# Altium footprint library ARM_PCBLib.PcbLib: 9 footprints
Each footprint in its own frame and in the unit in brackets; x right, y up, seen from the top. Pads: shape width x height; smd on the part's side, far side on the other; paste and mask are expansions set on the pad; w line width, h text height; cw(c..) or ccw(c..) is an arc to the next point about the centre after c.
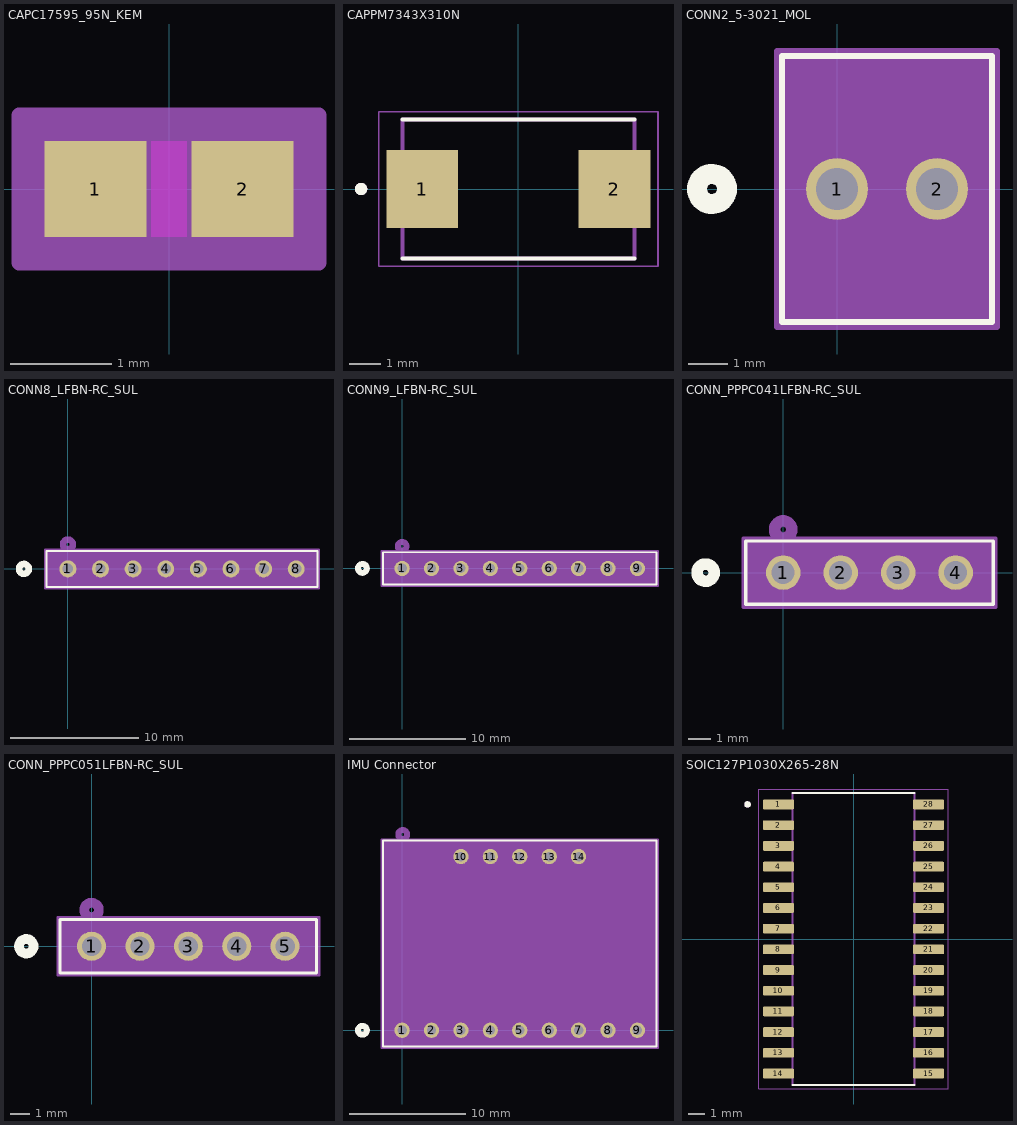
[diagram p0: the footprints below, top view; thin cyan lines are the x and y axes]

## CAPC17595_95N_KEM [mm]
pads (2):
  rect 1.006x0.95 smd paste+0 mask+0: 1(-0.728,0) 2(0.728,0)
Top Layer keep-out:
  region: -0.174,-0.424 -0.174,0.424 0.174,0.424 0.174,-0.424
Keep-Out Layer:
  region: -0.174,-0.475 -0.174,0.475 0.174,0.475 0.174,-0.475
Mechanical 13:
  lines w0.025: -0.875,-0.475 -0.875,0.475 ; -0.875,-0.475 -0.375,-0.475 -0.375,0.475 -0.875,0.475 ; -0.875,-0.475 0.875,-0.475 ; -0.875,-0.475 -0.875,0.475 ; -0.875,0.475 0.875,0.475 ; 0.875,-0.475 0.375,-0.475 0.375,0.475 0.875,0.475 ; 0.875,-0.475 0.875,0.475 ; 0.875,-0.475 0.875,0.475
Mechanical 15:
  region: 1.485,-0.729 -1.485,-0.729 -1.485,0.729 1.485,0.729
  lines w0.152: -1.485,-0.729 -1.485,0.729 1.485,0.729 1.485,-0.729 -1.485,-0.729
3D body "CAPC17595_95N_KEM.step": height 0.95, standoff 0, extent -0.875,-0.475 0.875,0.475

## CAPPM7343X310N [mm]
pads (2):
  rect 2.31x2.52 smd: 1(-3.1,0) 2(3.1,0)
Top Overlay:
  circle w0.2: c-5.08,0 r0.1
  lines w0.127: -3.75,-2.25 3.75,-2.25 ; -3.75,2.25 3.75,2.25
Mechanical 13:
  circle w0.2: c-5.08,0 r0.1
  lines w0.127: -3.75,-2.25 3.75,-2.25 3.75,2.25 -3.75,2.25 -3.75,-2.25
Mechanical 15:
  lines w0.05: -4.505,-2.5 4.505,-2.5 4.505,2.5 -4.505,2.5 -4.505,-2.5

## CONN2_5-3021_MOL [mil]
pads (2):
  round 62 / inner round 60 / far side round 62 hole 42 paste-99999 mask+0: 1(0,0) 2(100,0)
Top Overlay:
  circle w20: c-125,0 r15
  lines w6: -55,-133 -55,133 155,133 155,-133 -55,-133
Bottom Overlay:
  circle w20: c-125,0 r15
Mechanical 13:
  circle w20: c0,75 r15
  lines w1: -50,-128 -50,128 150,128 150,-128 -50,-128
Mechanical 15:
  region: 160,138 -60,138 -60,-138 160,-138
  lines w6: -60,-138 160,-138 160,138 -60,138 -60,-138

## CONN8_LFBN-RC_SUL [mil]
pads (8):
  round 52 / inner round 60 / far side round 52 hole 32 paste-99999 mask+0: 1(0,0) 2(100,0) 3(200,0) 4(300,0) 5(400,0) 6(500,0) 7(600,0) 8(700,0)
Top Overlay:
  circle w20: c-135,0 r15
  lines w6: -65,-55 -65,55 765,55 765,-55 -65,-55
Bottom Overlay:
  circle w20: c-135,0 r15
Mechanical 13:
  circle w20: c0,75 r15
  lines w1: -60,-50 -60,50 760,50 760,-50 -60,-50
Mechanical 15:
  region: 770,60 -70,60 -70,-60 770,-60
  lines w6: -70,-60 770,-60 770,60 -70,60 -70,-60

## CONN9_LFBN-RC_SUL [mil]
pads (9):
  round 52 / inner round 60 / far side round 52 hole 32 paste-99999 mask+0: 1(0,0) 2(100,0) 3(200,0) 4(300,0) 5(400,0) 6(500,0) 7(600,0) 8(700,0) 9(800,0)
Top Overlay:
  circle w20: c-135,0 r15
  lines w6: -65,-55 -65,55 865,55 865,-55 -65,-55
Bottom Overlay:
  circle w20: c-135,0 r15
Mechanical 13:
  circle w20: c0,75 r15
  lines w1: -60,-50 -60,50 860,50 860,-50 -60,-50
Mechanical 15:
  region: 870,60 -70,60 -70,-60 870,-60
  lines w6: -70,-60 870,-60 870,60 -70,60 -70,-60

## CONN_PPPC041LFBN-RC_SUL [mil]
pads (4):
  round 60 hole 40 paste-99999 mask-30: 1(0,0) 2(100,0) 3(200,0) 4(300,0)
Top Overlay:
  circle w20: c-135,0 r15
  lines w6: -65,-55 365.44,-55 365.44,55 -65,55 -65,-55
Bottom Overlay:
  circle w20: c-135,0 r15
Mechanical 13:
  circle w20: c0,75 r15
  lines w1: -60,-50 -60,50 360.02,50 360.02,-50 -60,-50
Mechanical 15:
  region: 371.85,60 -70,60 -70,-60 371.85,-60
  lines w6: -70,-60 -70,60 369.98,60 369.98,-60 -70,-60

## CONN_PPPC051LFBN-RC_SUL [mil]
pads (5):
  round 60 hole 40 paste-99999 mask-30: 1(0,0) 2(100,0) 3(200,0) 4(300,0) 5(400,0)
Top Overlay:
  circle w20: c-135,0 r15
  lines w6: -65,-55 -65,55 465,55 465,-55 -65,-55
Bottom Overlay:
  circle w20: c-135,0 r15
Mechanical 13:
  circle w20: c0,75 r15
  lines w1: -60,-50 -60,50 460,50 460,-50 -60,-50
Mechanical 15:
  region: 470,60 -70,60 -70,-60 470,-60
  lines w6: -70,-60 470,-60 470,60 -70,60 -70,-60

## IMU Connector [mil]
pads (14):
  round 52 / inner round 60 / far side round 52 hole 32 paste-99999 mask+0: 1(0,0) 2(100,0) 3(200,0) 4(300,0) 5(400,0) 6(500,0) 7(600,0) 8(700,0) 9(800,0) 10(200,590.55) 11(300,590.55) 12(400,590.55) 13(500,590.55) 14(600,590.55)
Top Overlay:
  circle w20: c-135,0 r15
  lines w6: -65,-55 865,-55 865,645.67 -65,645.67 -65,-55
Bottom Overlay:
  circle w20: c-135,0 r15
Mechanical 13:
  circle w20: c1.97,665.75 r15
  lines w1: -60,-50 -60,641.21 860,641.21 860,-50 -60,-50
Mechanical 15:
  region: 870,649.61 -70,649.61 -70,-60 870,-60
  lines w6: -70.87,-60 -70.87,649.61 870,649.61 870,-60 -70.87,-60

## SOIC127P1030X265-28N [mm]
pads (28):
  rrect25% 1.9x0.6 smd: 1(-4.605,8.255) 2(-4.605,6.985) 3(-4.605,5.715) 4(-4.605,4.445) 5(-4.605,3.175) 6(-4.605,1.905) 7(-4.605,0.635) 8(-4.605,-0.635) 9(-4.605,-1.905) 10(-4.605,-3.175) 11(-4.605,-4.445) 12(-4.605,-5.715) 13(-4.605,-6.985) 14(-4.605,-8.255) 15(4.605,-8.255) 16(4.605,-6.985) 17(4.605,-5.715) 18(4.605,-4.445) 19(4.605,-3.175) 20(4.605,-1.905) 21(4.605,-0.635) 22(4.605,0.635) 23(4.605,1.905) 24(4.605,3.175) 25(4.605,4.445) 26(4.605,5.715) 27(4.605,6.985) 28(4.605,8.255)
Top Overlay:
  circle w0.2: c-6.505,8.255 r0.1
  lines w0.127: -3.75,-8.95 3.75,-8.95 ; -3.75,8.95 3.75,8.95
Mechanical 13:
  circle w0.2: c-6.505,8.255 r0.1
  lines w0.127: -3.75,-8.95 3.75,-8.95 3.75,8.95 -3.75,8.95 -3.75,-8.95
Mechanical 15:
  lines w0.05: -5.805,-9.2 5.805,-9.2 5.805,9.2 -5.805,9.2 -5.805,-9.2
3D body "step_temp.STEP": height 2.65, standoff 0, extent -5.15,-8.95 5.15,8.95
